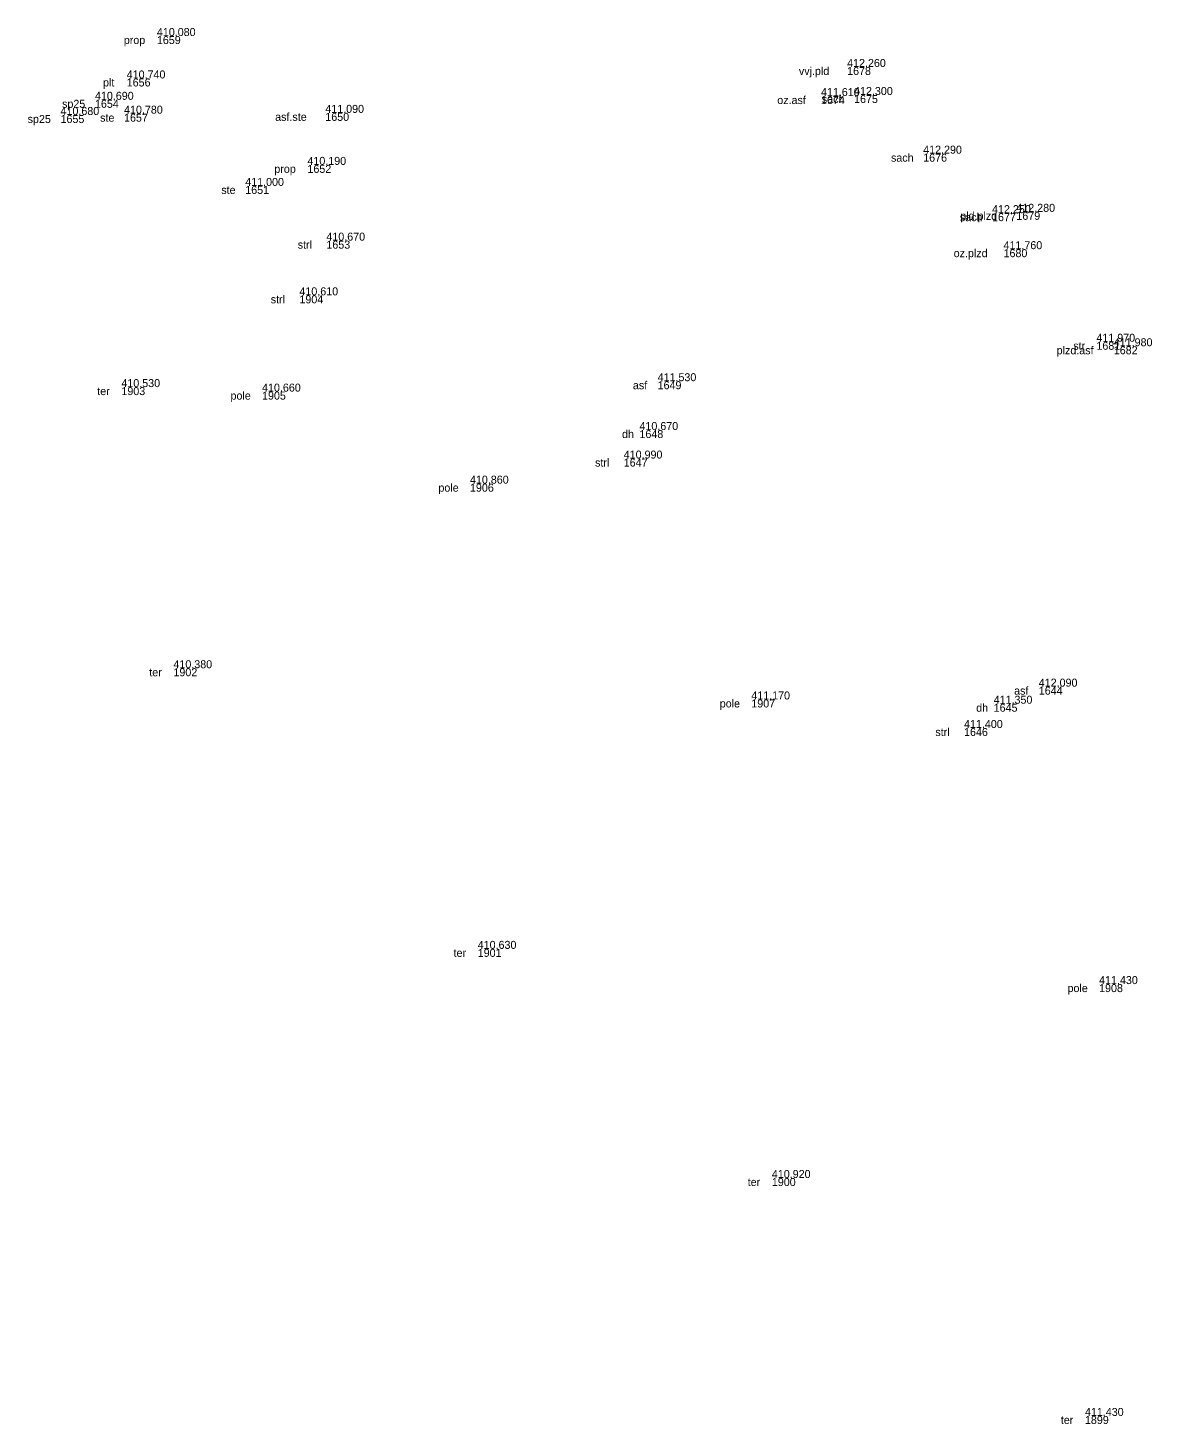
# Model space of a CAD drawing. Extents: x -747136 to -746138, y -1093274 to -1091717.
# Drawn here: x -746942.2 to -746900.1, y -1092324.9 to -1092272.6 of the extents above; entities that cross this region are included whole.
import ezdxf

# ---------------------------------------------------------------- set-up
doc = ezdxf.new("R2010")
doc.units = 0
for name, color, linetype in [('1029', 7, 'Continuous'), ('404', 7, 'Continuous'), ('424', 7, 'Continuous')]:
    doc.layers.add(name, color=color, linetype=linetype)

msp = doc.modelspace()

# ---------------------------------------------------------------- linework, layer by layer
at = {"layer": '404'}
for p, q in [((-746937.38, -1092272.89), (-746937.38, -1092272.89)), ((-746911.52, -1092274.05), (-746911.52, -1092274.05)), ((-746938.51, -1092274.48), (-746938.51, -1092274.48)), ((-746912.5, -1092275.14), (-746912.5, -1092275.14)), ((-746911.26, -1092275.1), (-746911.26, -1092275.1)), ((-746939.7, -1092275.28), (-746939.7, -1092275.28)), ((-746931.07, -1092275.77), (-746931.07, -1092275.77)), ((-746940.99, -1092275.85), (-746940.99, -1092275.85)), ((-746938.61, -1092275.8), (-746938.61, -1092275.8)), ((-746908.67, -1092277.3), (-746908.67, -1092277.3)), ((-746931.74, -1092277.72), (-746931.74, -1092277.72)), ((-746934.07, -1092278.51), (-746934.07, -1092278.51)), ((-746906.09, -1092279.53), (-746906.09, -1092279.53)), ((-746905.18, -1092279.48), (-746905.18, -1092279.48)), ((-746931.03, -1092280.56), (-746931.03, -1092280.56)), ((-746905.66, -1092280.88), (-746905.66, -1092280.88)), ((-746932.04, -1092282.61), (-746932.04, -1092282.61)), ((-746902.18, -1092284.35), (-746902.18, -1092284.35)), ((-746901.53, -1092284.52), (-746901.53, -1092284.52)), ((-746938.71, -1092286.05), (-746938.71, -1092286.05)), ((-746933.44, -1092286.22), (-746933.44, -1092286.22)), ((-746918.62, -1092285.83), (-746918.62, -1092285.83)), ((-746919.3, -1092287.66), (-746919.3, -1092287.66)), ((-746919.89, -1092288.73), (-746919.89, -1092288.73)), ((-746925.65, -1092289.67), (-746925.65, -1092289.67)), ((-746936.76, -1092296.59), (-746936.76, -1092296.59)), ((-746915.11, -1092297.76), (-746915.11, -1092297.76)), ((-746904.34, -1092297.28), (-746904.34, -1092297.28)), ((-746906.03, -1092297.92), (-746906.03, -1092297.92)), ((-746907.14, -1092298.83), (-746907.14, -1092298.83)), ((-746925.36, -1092307.11), (-746925.36, -1092307.11)), ((-746902.08, -1092308.43), (-746902.08, -1092308.43)), ((-746914.34, -1092315.7), (-746914.34, -1092315.7)), ((-746902.61, -1092324.62), (-746902.61, -1092324.62))]:
    msp.add_line(p, q, dxfattribs=at)

# ---------------------------------------------------------------- texts
at = {"layer": '1029'}
for s, p in [('410,080', (-746937.38, -1092272.89)), ('410,740', (-746938.51, -1092274.48)), ('412,260', (-746911.52, -1092274.05)), ('410,690', (-746939.7, -1092275.28)), ('411,610', (-746912.5, -1092275.14)), ('412,300', (-746911.26, -1092275.1)), ('410,680', (-746940.99, -1092275.85)), ('410,780', (-746938.61, -1092275.8)), ('411,090', (-746931.07, -1092275.77)), ('412,290', (-746908.67, -1092277.3)), ('410,190', (-746931.74, -1092277.72)), ('411,000', (-746934.07, -1092278.51)), ('412,250', (-746906.09, -1092279.53)), ('412,280', (-746905.18, -1092279.48)), ('410,670', (-746931.03, -1092280.56)), ('411,760', (-746905.66, -1092280.88)), ('410,610', (-746932.04, -1092282.61)), ('411,970', (-746902.18, -1092284.35)), ('411,980', (-746901.53, -1092284.52)), ('411,530', (-746918.62, -1092285.83)), ('410,530', (-746938.71, -1092286.05)), ('410,660', (-746933.44, -1092286.22)), ('410,670', (-746919.3, -1092287.66)), ('410,990', (-746919.89, -1092288.73)), ('410,860', (-746925.65, -1092289.67)), ('410,380', (-746936.76, -1092296.59)), ('412,090', (-746904.34, -1092297.28)), ('411,170', (-746915.11, -1092297.76)), ('411,350', (-746906.03, -1092297.92)), ('411,400', (-746907.14, -1092298.83)), ('410,630', (-746925.36, -1092307.11)), ('411,430', (-746902.08, -1092308.43)), ('410,920', (-746914.34, -1092315.7)), ('411,430', (-746902.61, -1092324.62))]:
    msp.add_text(s, height=0.3, dxfattribs=at).set_placement(p)
at = {"layer": '424'}
for s, p in [(' prop', (-746938.731, -1092273.19)), ('1659', (-746937.38, -1092273.19)), (' vvj.pld', (-746913.438, -1092274.35)), ('1678', (-746911.52, -1092274.35)), (' plt', (-746939.509, -1092274.78)), ('1656', (-746938.51, -1092274.78)), (' oz.asf', (-746914.248, -1092275.44)), ('1674', (-746912.5, -1092275.44)), (' sach', (-746912.578, -1092275.4)), ('1675', (-746911.26, -1092275.4)), (' sp25', (-746941.044, -1092275.58)), ('1654', (-746939.7, -1092275.58)), (' asf.ste', (-746933.061, -1092276.07)), ('1650', (-746931.07, -1092276.07)), (' sp25', (-746942.334, -1092276.15)), ('1655', (-746940.99, -1092276.15)), (' ste', (-746939.619, -1092276.1)), ('1657', (-746938.61, -1092276.1)), (' sach', (-746909.988, -1092277.6)), ('1676', (-746908.67, -1092277.6)), (' prop', (-746933.091, -1092278.02)), ('1652', (-746931.74, -1092278.02)), (' ste', (-746935.079, -1092278.81)), ('1651', (-746934.07, -1092278.81)), (' sach', (-746907.408, -1092279.83)), (' pld.plzd', (-746907.393, -1092279.78)), ('1677', (-746906.09, -1092279.83)), ('1679', (-746905.18, -1092279.78)), (' strl', (-746932.216, -1092280.86)), ('1653', (-746931.03, -1092280.86)), (' oz.plzd', (-746907.639, -1092281.18)), ('1680', (-746905.66, -1092281.18)), (' strl', (-746933.226, -1092282.91)), ('1904', (-746932.04, -1092282.91)), (' plzd.asf', (-746903.781, -1092284.82)), (' str', (-746903.158, -1092284.65)), ('1681', (-746902.18, -1092284.65)), ('1682', (-746901.53, -1092284.82)), (' ter', (-746939.726, -1092286.35)), ('1903', (-746938.71, -1092286.35)), (' pole', (-746934.734, -1092286.52)), ('1905', (-746933.44, -1092286.52)), (' asf', (-746919.657, -1092286.13)), ('1649', (-746918.62, -1092286.13)), (' dh', (-746920.065, -1092287.96)), ('1648', (-746919.3, -1092287.96)), (' strl', (-746921.076, -1092289.03)), ('1647', (-746919.89, -1092289.03)), (' pole', (-746926.944, -1092289.97)), ('1906', (-746925.65, -1092289.97)), (' ter', (-746937.776, -1092296.89)), ('1902', (-746936.76, -1092296.89)), (' pole', (-746916.404, -1092298.06)), ('1907', (-746915.11, -1092298.06)), (' asf', (-746905.377, -1092297.58)), ('1644', (-746904.34, -1092297.58)), (' dh', (-746906.795, -1092298.22)), ('1645', (-746906.03, -1092298.22)), (' strl', (-746908.326, -1092299.13)), ('1646', (-746907.14, -1092299.13)), (' ter', (-746926.376, -1092307.41)), ('1901', (-746925.36, -1092307.41)), (' pole', (-746903.374, -1092308.73)), ('1908', (-746902.08, -1092308.73)), (' ter', (-746915.356, -1092316)), ('1900', (-746914.34, -1092316)), (' ter', (-746903.626, -1092324.92)), ('1899', (-746902.61, -1092324.92))]:
    msp.add_text(s, height=0.3, dxfattribs=at).set_placement(p)

doc.saveas('drawing.dxf')
